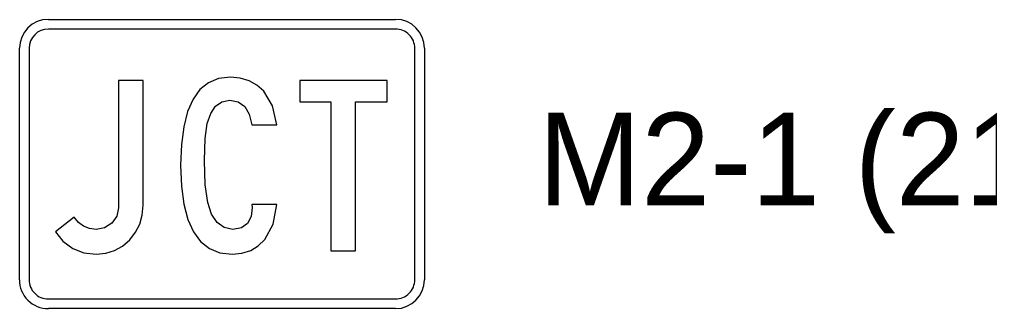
# Model space of a CAD drawing. Extents: x 620864 to 620948.6, y 415499.7 to 415559.1.
# Drawn here: x 620888.08 to 620892.272, y 415529.813 to 415531.063 of the extents above; entities that cross this region are included whole.
import ezdxf

# ---------------------------------------------------------------- set-up
doc = ezdxf.new("R2010")
doc.units = 0
doc.layers.add('SIGNS', color=7, linetype='Continuous')

msp = doc.modelspace()

# ---------------------------------------------------------------- linework, layer by layer
at = {"layer": 'SIGNS'}
for p, q in [((620888.205, 415531.0633), (620889.705, 415531.0633)), ((620889.705, 415531.0633), (620889.705, 415531.0633)), ((620889.705, 415531.0216), (620888.205, 415531.0216)), ((620888.08, 415529.9383), (620888.08, 415530.9383)), ((620888.1216, 415530.9383), (620888.1216, 415529.9383)), ((620889.7883, 415529.9383), (620889.7883, 415530.9383)), ((620889.83, 415530.9383), (620889.83, 415529.9383)), ((620888.205, 415529.8549), (620889.705, 415529.8549)), ((620889.705, 415529.8133), (620888.205, 415529.8133)), ((620888.205, 415529.8133), (620888.205, 415529.8133))]:
    msp.add_line(p, q, dxfattribs=at)
for points in [[(620888.205, 415531.0633), (620888.205, 415531.0633)], [(620888.08, 415530.9383), (620888.08, 415530.9383)], [(620889.83, 415529.9383), (620889.83, 415529.9383)], [(620889.705, 415529.8133), (620889.705, 415529.8133)]]:
    msp.add_lwpolyline(points, dxfattribs=at)
for points in [[(620889.1918, 415530.6077), (620889.1738, 415530.689), (620889.1355, 415530.753), (620889.1062, 415530.7792), (620889.0724, 415530.7982), (620889.0341, 415530.8094), (620888.9915, 415530.8133), (620888.9408, 415530.8071), (620888.8973, 415530.7894), (620888.8601, 415530.7596), (620888.8301, 415530.7181), (620888.8065, 415530.6645), (620888.7898, 415530.5991), (620888.7796, 415530.5219), (620888.7765, 415530.4328), (620888.7798, 415530.3427), (620888.7903, 415530.2647), (620888.8076, 415530.1987), (620888.8319, 415530.1448), (620888.863, 415530.1026), (620888.9013, 415530.0727), (620888.9466, 415530.0548), (620888.9989, 415530.0489), (620889.0415, 415530.0527), (620889.0794, 415530.0644), (620889.1121, 415530.084), (620889.14, 415530.1117), (620889.1758, 415530.1777), (620889.1918, 415530.2627), (620889.0843, 415530.2627), (620889.085, 415530.2508), (620889.0808, 415530.2118), (620889.0654, 415530.1817), (620889.0388, 415530.1621), (620889.0021, 415530.1558), (620888.9648, 415530.1631), (620888.9345, 415530.1849), (620888.9106, 415530.2212), (620888.8937, 415530.2724), (620888.8831, 415530.3476), (620888.8797, 415530.4533), (620888.8826, 415530.5478), (620888.8916, 415530.6129), (620888.9065, 415530.6571), (620888.9277, 415530.6886), (620888.955, 415530.7075), (620888.9887, 415530.7138), (620889.0255, 415530.7071), (620889.0537, 415530.6873), (620889.0732, 415530.6539), (620889.0843, 415530.6077)], [(620888.2362, 415530.1455), (620888.2672, 415530.1043), (620888.3103, 415530.0736), (620888.3585, 415530.0549), (620888.4113, 415530.0489), (620888.453, 415530.0527), (620888.4913, 415530.0641), (620888.5255, 415530.0835), (620888.5566, 415530.1108), (620888.5819, 415530.143), (620888.5999, 415530.1788), (620888.6108, 415530.2176), (620888.6145, 415530.2597), (620888.6145, 415530.7988), (620888.5078, 415530.7988), (620888.5078, 415530.2491), (620888.5005, 415530.2129), (620888.4791, 415530.1829), (620888.4478, 415530.1626), (620888.4113, 415530.1558), (620888.3824, 415530.159), (620888.3571, 415530.1689), (620888.3354, 415530.1854), (620888.317, 415530.2086)], [(620889.4255, 415530.0633), (620889.5323, 415530.0633), (620889.5323, 415530.7064), (620889.6695, 415530.7064), (620889.6695, 415530.7988), (620889.2912, 415530.7988), (620889.2912, 415530.7064), (620889.4255, 415530.7064)]]:
    msp.add_lwpolyline(points, close=True, dxfattribs=at)
for centre, radius, start, end in [((620888.205, 415530.9383), 0.125, 90.0002, 179.9998), ((620889.705, 415530.9383), 0.125, 0, 90), ((620888.205, 415530.9383), 0.0833, 90.0002, 179.9998), ((620889.705, 415530.9383), 0.0833, 0, 90.0002), ((620888.205, 415529.9383), 0.125, 179.9998, 270), ((620888.205, 415529.9383), 0.0833, 179.9998, 270.0001), ((620889.705, 415529.9383), 0.125, 270.0001, 360), ((620889.705, 415529.9383), 0.0833, 270.0001, 0.0003)]:
    msp.add_arc(centre, radius, start, end, dxfattribs=at)

# ---------------------------------------------------------------- texts
msp.add_text('M2-1 (21"x15")', height=0.4, rotation=0, dxfattribs=at).set_placement((620890.321, 415530.2596))

doc.saveas('drawing.dxf')
